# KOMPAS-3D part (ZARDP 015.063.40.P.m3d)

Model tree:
1. Плоскость XY
2. Плоскость ZX
3. Плоскость ZY
4. Ось X
5. Ось Y
6. Ось Z
7. Начало координат
8. Смещенная плоскость:2
     Расстояние = 60
9. Булева операция:1
10. Булева операция:2
